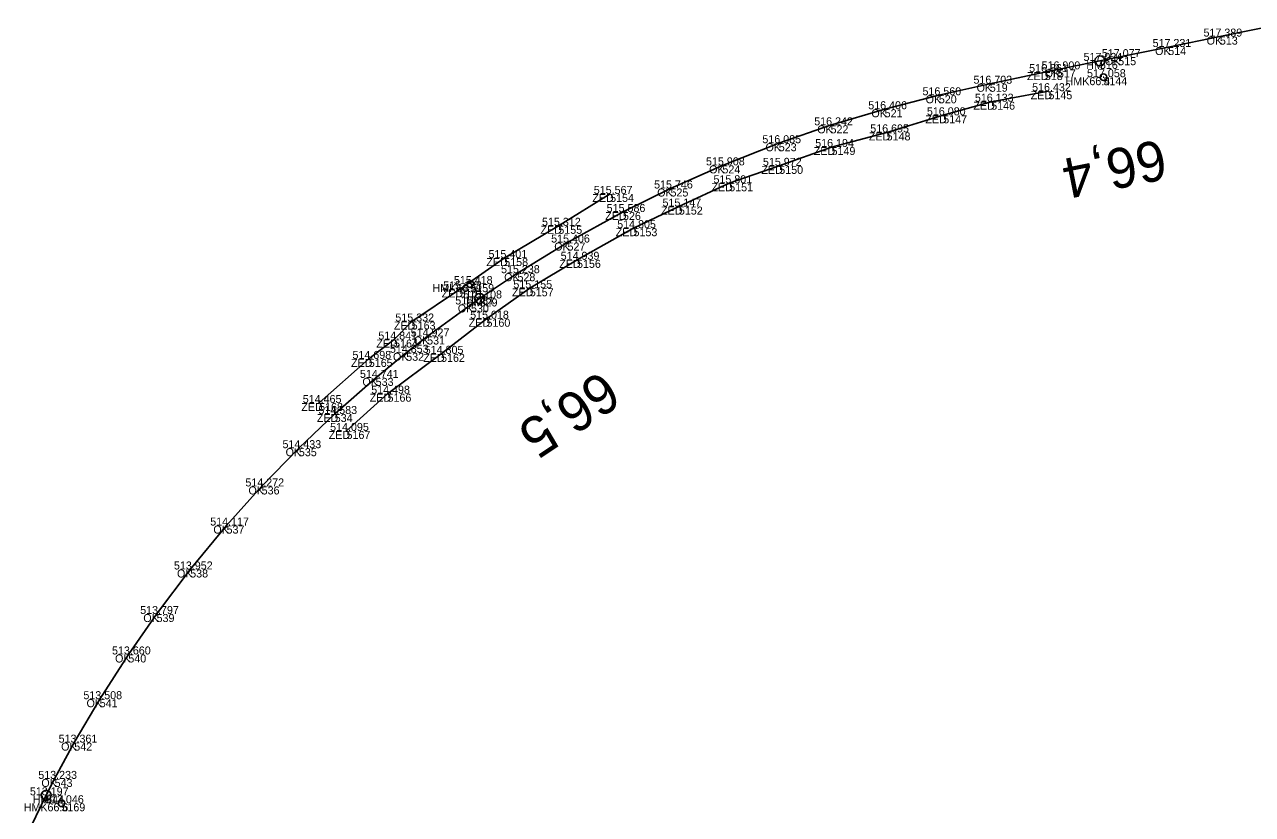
# Model space of a CAD drawing. Extents: x -621782 to -610392, y -1141853 to -1122321.
# Drawn here: x -621514.7 to -621330.7, y -1123519.4 to -1123401.1 of the extents above; entities that cross this region are included whole.
import ezdxf

# ---------------------------------------------------------------- set-up
doc = ezdxf.new("R2010")
doc.units = 0
for name, color, linetype in [('Vrstva 1', 7, 'Continuous'), ('Vrstva 13', 7, 'Continuous'), ('Vrstva 60', 7, 'Continuous'), ('Vrstva 61', 7, 'Continuous'), ('Vrstva 62', 7, 'Continuous'), ('Vrstva 7', 7, 'Continuous')]:
    doc.layers.add(name, color=color, linetype=linetype)

msp = doc.modelspace()

# ---------------------------------------------------------------- linework, layer by layer
at = {"layer": 'Vrstva 1'}
msp.add_lwpolyline([(-621326.68, -1123401.09), (-621335.56, -1123402.89), (-621343.29, -1123404.45), (-621350.79, -1123405.97), (-621353.54, -1123406.53), (-621359.83, -1123407.8), (-621361.79, -1123408.2), (-621370.04, -1123409.95), (-621377.68, -1123411.68), (-621385.8, -1123413.77), (-621393.91, -1123416.18), (-621401.67, -1123418.86), (-621410.12, -1123422.18), (-621417.9, -1123425.64), (-621425.02, -1123429.16), (-621433.34, -1123433.74), (-621440.84, -1123438.33), (-621446.51, -1123442.11), (-621447.8, -1123443.01), (-621454.38, -1123447.81), (-621457.51, -1123450.25), (-621462.09, -1123454.01), (-621468.23, -1123459.42), (-621473.6, -1123464.54), (-621479.18, -1123470.27), (-621484.44, -1123476.13), (-621489.89, -1123482.71), (-621494.93, -1123489.38), (-621499.16, -1123495.44), (-621503.45, -1123502.14), (-621507.26, -1123508.65), (-621510.21, -1123514.08), (-621511.47, -1123516.54), (-621514.51, -1123522.8)], dxfattribs=at)
at = {"layer": 'Vrstva 13'}
for points in [[(-621361.25, -1123411.07), (-621369.83, -1123412.64), (-621377.02, -1123414.68), (-621385.5, -1123417.24), (-621393.76, -1123419.43), (-621401.6, -1123422.25), (-621409.1, -1123424.86), (-621416.64, -1123428.35), (-621423.44, -1123431.59), (-621431.91, -1123436.32), (-621438.99, -1123440.59), (-621445.48, -1123445.15), (-621452.29, -1123450.41), (-621460.31, -1123456.38), (-621466.46, -1123461.96)], [(-621470.57, -1123457.77), (-621463.12, -1123451.17), (-621459.33, -1123448.27), (-621456.69, -1123445.57), (-621449.53, -1123440.76), (-621442.82, -1123436.06), (-621434.71, -1123431.23), (-621426.95, -1123426.46)]]:
    msp.add_lwpolyline(points, dxfattribs=at)
at = {"layer": 'Vrstva 60'}
for p, q in [((-621335.56, -1123402.89), (-621335.56, -1123402.89)), ((-621350.79, -1123405.97), (-621350.79, -1123405.97)), ((-621343.29, -1123404.45), (-621343.29, -1123404.45)), ((-621359.83, -1123407.8), (-621359.83, -1123407.8)), ((-621353.54, -1123406.53), (-621353.54, -1123406.53)), ((-621361.79, -1123408.2), (-621361.79, -1123408.2)), ((-621353.01, -1123408.97), (-621353.01, -1123408.97)), ((-621370.04, -1123409.95), (-621370.04, -1123409.95)), ((-621361.25, -1123411.07), (-621361.25, -1123411.07)), ((-621377.68, -1123411.68), (-621377.68, -1123411.68)), ((-621369.83, -1123412.64), (-621369.83, -1123412.64)), ((-621385.8, -1123413.77), (-621385.8, -1123413.77)), ((-621377.02, -1123414.68), (-621377.02, -1123414.68)), ((-621393.91, -1123416.18), (-621393.91, -1123416.18)), ((-621401.67, -1123418.86), (-621401.67, -1123418.86)), ((-621385.5, -1123417.24), (-621385.5, -1123417.24)), ((-621393.76, -1123419.43), (-621393.76, -1123419.43)), ((-621410.12, -1123422.18), (-621410.12, -1123422.18)), ((-621401.6, -1123422.25), (-621401.6, -1123422.25)), ((-621417.9, -1123425.64), (-621417.9, -1123425.64)), ((-621409.1, -1123424.86), (-621409.1, -1123424.86)), ((-621426.95, -1123426.46), (-621426.95, -1123426.46)), ((-621425.02, -1123429.16), (-621425.02, -1123429.16)), ((-621416.64, -1123428.35), (-621416.64, -1123428.35)), ((-621434.71, -1123431.23), (-621434.71, -1123431.23)), ((-621423.44, -1123431.59), (-621423.44, -1123431.59)), ((-621433.34, -1123433.74), (-621433.34, -1123433.74)), ((-621442.82, -1123436.06), (-621442.82, -1123436.06)), ((-621431.91, -1123436.32), (-621431.91, -1123436.32)), ((-621440.84, -1123438.33), (-621440.84, -1123438.33)), ((-621449.53, -1123440.76), (-621449.53, -1123440.76)), ((-621447.91, -1123439.96), (-621447.91, -1123439.96)), ((-621438.99, -1123440.59), (-621438.99, -1123440.59)), ((-621446.51, -1123442.11), (-621446.51, -1123442.11)), ((-621447.8, -1123443.01), (-621447.8, -1123443.01)), ((-621456.69, -1123445.57), (-621456.69, -1123445.57)), ((-621445.48, -1123445.15), (-621445.48, -1123445.15)), ((-621459.33, -1123448.27), (-621459.33, -1123448.27)), ((-621454.38, -1123447.81), (-621454.38, -1123447.81)), ((-621457.51, -1123450.25), (-621457.51, -1123450.25)), ((-621463.12, -1123451.17), (-621463.12, -1123451.17)), ((-621452.29, -1123450.41), (-621452.29, -1123450.41)), ((-621462.09, -1123454.01), (-621462.09, -1123454.01)), ((-621460.31, -1123456.38), (-621460.31, -1123456.38)), ((-621470.57, -1123457.77), (-621470.57, -1123457.77)), ((-621468.23, -1123459.42), (-621468.23, -1123459.42)), ((-621466.46, -1123461.96), (-621466.46, -1123461.96)), ((-621473.6, -1123464.54), (-621473.6, -1123464.54)), ((-621479.18, -1123470.27), (-621479.18, -1123470.27)), ((-621484.44, -1123476.13), (-621484.44, -1123476.13)), ((-621489.89, -1123482.71), (-621489.89, -1123482.71)), ((-621494.93, -1123489.38), (-621494.93, -1123489.38)), ((-621499.16, -1123495.44), (-621499.16, -1123495.44)), ((-621503.45, -1123502.14), (-621503.45, -1123502.14)), ((-621507.26, -1123508.65), (-621507.26, -1123508.65)), ((-621510.21, -1123514.08), (-621510.21, -1123514.08)), ((-621511.47, -1123516.54), (-621511.47, -1123516.54)), ((-621509.19, -1123517.73), (-621509.19, -1123517.73))]:
    msp.add_line(p, q, dxfattribs=at)
at = {"layer": 'Vrstva 7'}
for p, q in [((-621352.96, -1123408.96), (-621353.06, -1123408.98)), ((-621447.87, -1123439.93), (-621447.95, -1123439.98)), ((-621509.16, -1123517.69), (-621509.21, -1123517.78))]:
    msp.add_line(p, q, dxfattribs=at)
for centre, radius in [((-621353.54, -1123406.53), 0.75), ((-621353.01, -1123408.97), 0.5), ((-621447.91, -1123439.96), 0.5), ((-621446.51, -1123442.11), 0.75), ((-621511.47, -1123516.54), 0.75), ((-621509.19, -1123517.73), 0.5)]:
    msp.add_circle(centre, radius, dxfattribs=at)

# ---------------------------------------------------------------- texts
at = {"layer": 'Vrstva 60'}
for s, p in [('513', (-621335.56, -1123404.09)), ('515', (-621350.79, -1123407.17)), ('514', (-621343.29, -1123405.65)), ('517', (-621359.83, -1123409)), ('516', (-621353.54, -1123407.73)), ('518', (-621361.79, -1123409.4)), ('5144', (-621353.01, -1123410.17)), ('520', (-621377.68, -1123412.88)), ('519', (-621370.04, -1123411.15)), ('5145', (-621361.25, -1123412.27)), ('5146', (-621369.83, -1123413.84)), ('521', (-621385.8, -1123414.97)), ('5147', (-621377.02, -1123415.88)), ('522', (-621393.91, -1123417.38)), ('523', (-621401.67, -1123420.06)), ('5148', (-621385.5, -1123418.44)), ('5149', (-621393.76, -1123420.63)), ('524', (-621410.12, -1123423.38)), ('5150', (-621401.6, -1123423.45)), ('525', (-621417.9, -1123426.84)), ('5151', (-621409.1, -1123426.06)), ('5154', (-621426.95, -1123427.66)), ('526', (-621425.02, -1123430.36)), ('5152', (-621416.64, -1123429.55)), ('5155', (-621434.71, -1123432.43)), ('5153', (-621423.44, -1123432.79)), ('527', (-621433.34, -1123434.94)), ('5158', (-621442.82, -1123437.26)), ('5156', (-621431.91, -1123437.53)), ('528', (-621440.84, -1123439.53)), ('5161', (-621449.53, -1123441.96)), ('5159', (-621447.91, -1123441.16)), ('5157', (-621438.99, -1123441.79)), ('529', (-621446.51, -1123443.31)), ('530', (-621447.8, -1123444.21)), ('5163', (-621456.69, -1123446.77)), ('5160', (-621445.48, -1123446.35)), ('5164', (-621459.33, -1123449.47)), ('531', (-621454.38, -1123449.01)), ('532', (-621457.51, -1123451.45)), ('5165', (-621463.12, -1123452.37)), ('5162', (-621452.29, -1123451.61)), ('533', (-621462.09, -1123455.21)), ('5166', (-621460.31, -1123457.58)), ('5168', (-621470.57, -1123458.97)), ('534', (-621468.23, -1123460.62)), ('5167', (-621466.46, -1123463.16)), ('535', (-621473.6, -1123465.74)), ('536', (-621479.18, -1123471.47)), ('537', (-621484.44, -1123477.33)), ('538', (-621489.89, -1123483.91)), ('539', (-621494.93, -1123490.58)), ('540', (-621499.16, -1123496.64)), ('541', (-621503.45, -1123503.34)), ('542', (-621507.26, -1123509.84)), ('543', (-621510.21, -1123515.28)), ('544', (-621511.47, -1123517.74)), ('5169', (-621509.19, -1123518.93))]:
    msp.add_text(s, height=1.2, dxfattribs=at).set_placement(p)
at = {"layer": 'Vrstva 61'}
for s, p in [('517.389', (-621338.01, -1123402.89)), ('517.231', (-621345.64, -1123404.45)), ('517.024', (-621355.99, -1123406.53)), ('517.077', (-621353.25, -1123405.97)), ('516.861', (-621364.15, -1123408.2)), ('516.900', (-621362.28, -1123407.8)), ('517.058', (-621355.47, -1123408.97)), ('516.703', (-621372.49, -1123409.95)), ('516.560', (-621380.13, -1123411.68)), ('516.133', (-621372.28, -1123412.64)), ('516.432', (-621363.7, -1123411.07)), ('516.406', (-621388.26, -1123413.77)), ('516.080', (-621379.47, -1123414.68)), ('516.242', (-621396.36, -1123416.18)), ('516.695', (-621387.96, -1123417.24)), ('516.085', (-621404.13, -1123418.86)), ('516.194', (-621396.21, -1123419.43)), ('515.908', (-621412.58, -1123422.18)), ('515.972', (-621404.05, -1123422.25)), ('515.746', (-621420.36, -1123425.64)), ('515.801', (-621411.46, -1123424.86)), ('515.567', (-621429.4, -1123426.46)), ('515.586', (-621427.47, -1123429.16)), ('515.147', (-621419.1, -1123428.35)), ('515.312', (-621437.16, -1123431.23)), ('514.805', (-621425.89, -1123431.59)), ('515.406', (-621435.79, -1123433.74)), ('515.401', (-621445.18, -1123436.06)), ('514.939', (-621434.36, -1123436.32)), ('515.238', (-621443.3, -1123438.33)), ('515.418', (-621450.37, -1123439.96)), ('515.188', (-621451.98, -1123440.76)), ('515.108', (-621448.96, -1123442.11)), ('515.155', (-621441.45, -1123440.59)), ('515.081', (-621450.16, -1123443.01)), ('515.332', (-621459.14, -1123445.57)), ('515.018', (-621447.93, -1123445.15)), ('514.927', (-621456.84, -1123447.81)), ('514.841', (-621461.69, -1123448.27)), ('514.698', (-621465.57, -1123451.17)), ('514.853', (-621459.96, -1123450.25)), ('514.805', (-621454.74, -1123450.41)), ('514.741', (-621464.45, -1123454.01)), ('514.498', (-621462.76, -1123456.38)), ('514.465', (-621473.02, -1123457.77)), ('514.583', (-621470.68, -1123459.42)), ('514.095', (-621468.92, -1123461.96)), ('514.433', (-621476.06, -1123464.54)), ('514.272', (-621481.62, -1123470.27)), ('514.117', (-621486.89, -1123476.13)), ('513.952', (-621492.33, -1123482.71)), ('513.797', (-621497.39, -1123489.38)), ('513.660', (-621501.61, -1123495.44)), ('513.508', (-621505.9, -1123502.14)), ('513.361', (-621509.61, -1123508.65)), ('513.233', (-621512.66, -1123514.08)), ('513.197', (-621513.92, -1123516.54)), ('513.046', (-621511.64, -1123517.73))]:
    msp.add_text(s, height=1.2, dxfattribs=at).set_placement(p)
at = {"layer": 'Vrstva 62'}
for s, p in [('OK', (-621337.54, -1123404.09)), ('OK', (-621352.78, -1123407.17)), ('OK', (-621345.27, -1123405.65)), ('OK', (-621361.82, -1123409)), ('HM', (-621355.58, -1123407.73)), ('ZED', (-621364.46, -1123409.4)), ('HMK66.4', (-621358.68, -1123410.17)), ('OK', (-621379.66, -1123412.88)), ('OK', (-621372.02, -1123411.15)), ('ZED', (-621363.92, -1123412.27)), ('ZED', (-621372.5, -1123413.84)), ('OK', (-621387.79, -1123414.97)), ('ZED', (-621379.7, -1123415.88)), ('OK', (-621395.9, -1123417.38)), ('OK', (-621403.66, -1123420.06)), ('ZED', (-621388.17, -1123418.44)), ('ZED', (-621396.43, -1123420.63)), ('OK', (-621412.11, -1123423.38)), ('ZED', (-621404.28, -1123423.45)), ('OK', (-621419.89, -1123426.84)), ('ZED', (-621411.77, -1123426.06)), ('ZED', (-621429.62, -1123427.66)), ('ZED', (-621427.69, -1123430.36)), ('ZED', (-621419.32, -1123429.55)), ('ZED', (-621437.39, -1123432.43)), ('ZED', (-621426.11, -1123432.79)), ('OK', (-621435.32, -1123434.94)), ('ZED', (-621445.5, -1123437.26)), ('ZED', (-621434.58, -1123437.53)), ('OK', (-621442.83, -1123439.53)), ('HMK66.5', (-621453.58, -1123441.16)), ('ZED', (-621452.2, -1123441.96)), ('ZED', (-621441.66, -1123441.79)), ('HM', (-621448.54, -1123443.31)), ('OK', (-621449.78, -1123444.21)), ('ZED', (-621459.36, -1123446.77)), ('ZED', (-621448.15, -1123446.35)), ('ZED', (-621462, -1123449.47)), ('OK', (-621456.37, -1123449.01)), ('OK', (-621459.5, -1123451.45)), ('ZED', (-621465.79, -1123452.37)), ('ZED', (-621454.96, -1123451.61)), ('OK', (-621464.08, -1123455.21)), ('ZED', (-621462.98, -1123457.58)), ('ZED', (-621473.24, -1123458.97)), ('ZED', (-621470.91, -1123460.62)), ('ZED', (-621469.13, -1123463.16)), ('OK', (-621475.59, -1123465.74)), ('OK', (-621481.16, -1123471.47)), ('OK', (-621486.42, -1123477.33)), ('OK', (-621491.87, -1123483.91)), ('OK', (-621496.92, -1123490.58)), ('OK', (-621501.15, -1123496.64)), ('OK', (-621505.43, -1123503.34)), ('OK', (-621509.24, -1123509.84)), ('OK', (-621512.2, -1123515.28)), ('HM', (-621513.5, -1123517.74)), ('HMK66.6', (-621514.85, -1123518.93))]:
    msp.add_text(s, height=1.2, dxfattribs=at).set_placement(p)
at = {"layer": 'Vrstva 7'}
for s, rotation, p in [('66,4', 191.4742, (-621344.29, -1123418.24)), ('66,5', 213.6714, (-621428.19, -1123452.73))]:
    msp.add_text(s, height=6, rotation=rotation, dxfattribs=at).set_placement(p)

doc.saveas('drawing.dxf')
